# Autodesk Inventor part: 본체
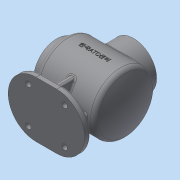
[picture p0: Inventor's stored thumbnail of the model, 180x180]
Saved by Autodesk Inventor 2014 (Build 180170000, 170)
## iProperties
Created: 2023-01
Part Number: 본체
Material: 일반
Document SubType Name: Modeling
Designer: dg
Density: 1 g/cm^3
Appearance: 기본값
Author: dg
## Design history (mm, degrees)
sketch "스케치1"
  geometry: L1 (0, 0)-(122, 0); L2 (0, 38)-(12, 38); L3 (12, 38)-(12, 50); L4 (12, 50)-(111.087, 50); L5 (0, 38)-(0, 27); L6 (0, 27)-(17, 27); L7 (17, 27)-(17, 45); L8 (17, 45)-(107.83, 45); A1 r 120 centre (2, 0) between (122, 0) and (111.087, 50); A2 r 115 centre (2, 0) between (117, 0) and (107.83, 45)
  constraints: 16 end point, 4 point on circle, 3 parallel, 2 centre point, 2 horizontal alignment, 2 perpendicular, 1 concentric, 1 horizontal, 1 point on line, 1 vertical alignment
  dimensions: "d0" = 122 distance of L1.start L1.end; "d1" = 54 diameter of L6 L1; "d2" = 76 diameter of L2 L1; "d3" = 100 diameter of L4 L1; "d4" = 17 distance of L5.end L6.end; "d5" = 110 horizontal distance of L1.end L3.end; "d6" = 120 radius of A1; "d7" = 90 diameter of L8 L1; "d8" = 5 radial gap between concentric circles of A1 A2
revolve "회전1" sketch "스케치1" stored, may be unused: angle "d9" = 90 deg
fillet "모깎기1" dims "d10" = 8
sketch "스케치2"
  geometry: C1 r 38 at (0, 0) reference; 1 further point
  constraints: 1 vertical alignment
  dimensions: "d11" = 32.5 distance of C1.centre point (0, 32.5)
hole "구멍1" sketch "스케치2" at (0, 32.5) diameter "d12" = 3.242; stored, may be unused: countersink angle "d16" = 90 deg, drill point angle "d18" = 118 deg; dims "d13" = 8, "d14" = 4, "d15" = 2, "d17" = 10
node "작업 평면1"
sketch "스케치3"
  geometry: L1 (0, 38)-(0, -38) reference; C1 r 38 at (-63, 0); A1 r 120 centre (-2, 0) between (-113.243, 45) and (-113.243, -45) reference; 2 further points
  constraints: 1 centre point, 1 horizontal alignment, 1 midpoint
  dimensions: "d23" = 76 diameter of C1; "d24" = 63 distance of point (0, 0) C1.centre
extrude "돌출1" join sketch "스케치3" stored distance "d25" = 10; taper "d26" = 0 deg
sketch "스케치4"
  geometry: C1 r 38 at (0, 0) reference; C2 r 27 at (0, 0); 1 further point
  constraints: 1 centre point, 1 coincident
  dimensions: "d27" = 54 diameter of C2
extrude "돌출2" cut sketch "스케치4" stored distance "d28" = 10; taper "d29" = 0 deg
chamfer "모따기1" distance "d30" = 1; stored, may be unused: second distance "d31" = 2, angle "d32" = 45 deg
sketch "스케치5"
  geometry: C1 r 38 at (0, 0) reference; 2 further points
  constraints: 1 vertical alignment
  dimensions: "d33" = 32.5 distance of C1.centre point (0, 32.5)
hole "구멍2" sketch "스케치5" at (0, 32.5) diameter "d34" = 3.242; stored, may be unused: countersink angle "d38" = 90 deg, drill point angle "d40" = 118 deg; dims "d35" = 8, "d36" = 4, "d37" = 2, "d39" = 10
fillet "모깎기2" dims "d44" = 3
chamfer "모따기2" distance "d45" = 1; stored, may be unused: second distance "d46" = 2, angle "d47" = 45 deg
fillet "모깎기3" dims "d48" = 3
node "작업 평면2"
sketch "스케치6"
  geometry: L1 (0, 38)-(0, -38) reference; L2 (-80, 46)-(-46, 46); L3 (-46, -46)-(-80, -46); L4 (-126, 0)-(0, 0); A1 r 46 centre (-46, 0) between (-46, -46) and (-46, 46); A2 r 46 centre (-80, 0) between (-80, 46) and (-80, -46); 2 further points
  constraints: 6 end point, 6 point on circle, 2 centre point, 2 perpendicular, 2 tangent, 1 coincident, 1 equal radius, 1 horizontal alignment, 1 midpoint, 1 parallel
  dimensions: "d50" = 92 distance between parallel lines of L3 L2; "d51" = 126 distance of L4.start point (0, 0)
extrude "돌출3" join sketch "스케치6" distance "d52" = 10; taper "d53" = 0 deg
sketch "스케치7"
  geometry: L1 (46, -46)-(80, -46) reference; L2 (80, 46)-(46, 46) reference; L3 (63, 46)-(63, -46); C1 r 4.5 at (33, 30); C2 r 4.5 at (33, -30); C3 r 4.5 at (93, -30); C4 r 4.5 at (93, 30); A1 r 46 centre (46, 0) between (46, 46) and (46, -46) reference; 1 further point
  constraints: 4 centre point, 3 equal radius, 2 end point, 2 horizontal alignment, 2 midpoint, 2 vertical alignment
  dimensions: "d54" = 60 distance of C4.centre C1.centre; "d55" = 60 distance of C2.centre C1.centre; "d56" = 30 vertical distance of A1.centre C2.centre; "d57" = 9 diameter of C1; "d58" = 30 distance from line of C4.centre L3
extrude "돌출4" cut sketch "스케치7" stored distance "d59" = 10; taper "d60" = 0 deg
sketch "스케치8"
  geometry: L1 (80, 46)-(46, 46) reference; L2 (58, 35)-(68, 35); L3 (68, 35)-(68, -35); L4 (68, -35)-(58, -35); L5 (58, -35)-(58, 35); A1 r 46 centre (46, 0) between (46, 46) and (46, -46) reference; 5 further points
  constraints: 8 end point, 3 midpoint, 2 parallel, 1 horizontal, 1 horizontal alignment, 1 perpendicular, 1 point on circle, 1 vertical alignment
  dimensions: "d61" = 10 distance of L2.start L2.end; "d62" = 70 distance of L4.end L2.start
extrude "돌출5" join sketch "스케치8" stored distance "d63" = 10; taper "d64" = 0 deg
sketch "스케치9"
  geometry: L1 (10.974, 32.5)-(10, 34.121) reference; L2 (10, 34.121)-(0, 34.121) reference; L3 (0, 34.121)-(0, 38) reference; L4 (0, 38)-(9, 38) reference; L5 (12, 41)-(12, 42) reference; L6 (20, 50)-(22, 50) reference; L7 (25, 53)-(25, 64) reference; L8 (25, 64)-(28.879, 64) reference; L9 (28.879, 64)-(28.879, 54) reference; L10 (28.879, 54)-(30.5, 53.026) reference; L11 (30.5, 53.026)-(32.121, 54) reference; L12 (32.121, 54)-(32.121, 64) reference; L13 (32.121, 64)-(35, 64) reference; L14 (35, 64)-(36, 63) reference; L15 (36, 63)-(36, 45) reference; L16 (36, 45)-(20, 45) reference; L17 (17, 42)-(17, 27) reference; L18 (17, 27)-(1, 27) reference; L19 (1, 27)-(0, 28) reference; L20 (0, 28)-(0, 30.879) reference; L21 (0, 30.879)-(10, 30.879) reference; L22 (10, 30.879)-(10.974, 32.5) reference; L23 (126, -70)-(126, -80) reference; L24 (126, -80)-(0, -80) reference; L25 (0, -80)-(0, -70) reference; L26 (0, -70)-(58, -70) reference; L27 (58, -70)-(58, -50) reference; L28 (58, -50)-(20, -50) reference; L29 (12, -42)-(12, -41) reference; L30 (9, -38)-(0, -38) reference; L31 (0, -38)-(0, -34.121) reference; L32 (0, -34.121)-(10, -34.121) reference; L33 (10, -34.121)-(10.974, -32.5) reference; L34 (10.974, -32.5)-(10, -30.879) reference; L35 (10, -30.879)-(0, -30.879) reference; L36 (0, -30.879)-(0, -28) reference; L37 (0, -28)-(1, -27) reference; L38 (1, -27)-(17, -27) reference; L39 (17, -27)-(17, -42) reference; L40 (20, -45)-(105.827, -45) reference; L41 (105.827, 45)-(90, 45) reference; L42 (90, 45)-(90, 63) reference; L43 (90, 63)-(91, 64) reference; L44 (91, 64)-(93.879, 64) reference; L45 (93.879, 64)-(93.879, 54) reference; L46 (93.879, 54)-(95.5, 53.026) reference; L47 (95.5, 53.026)-(97.121, 54) reference; L48 (97.121, 54)-(97.121, 64) reference; L49 (97.121, 64)-(101, 64) reference; L50 (101, 64)-(101, 53) reference; L51 (104, 50)-(105.827, 50) reference; L52 (105.827, -50)-(68, -50) reference; L53 (68, -50)-(68, -70) reference; L54 (68, -70)-(126, -70) reference; L55 (91, 64)-(35, 64) reference; L56 (63, -80)-(63, 64); L57 (23, -70)-(28.359, -50); A1 r 3 centre (9, 41) between (9, 38) and (12, 41) reference; A2 r 8 centre (20, 42) between (20, 50) and (12, 42) reference; A3 r 3 centre (20, 42) between (20, 45) and (17, 42) reference; A4 r 8 centre (20, -42) between (12, -42) and (20, -50) reference; A5 r 3 centre (9, -41) between (12, -41) and (9, -38) reference; A6 r 3 centre (20, -42) between (17, -42) and (20, -45) reference; A7 r 3 centre (105.827, -42) between (105.827, -45) and (108.608, -43.125) reference; A8 r 115 centre (2, 0) between (108.608, -43.125) and (108.608, 43.125) reference; A9 r 3 centre (105.827, 42) between (108.608, 43.125) and (105.827, 45) reference; A10 r 8 centre (105.827, 42) between (113.243, 45) and (105.827, 50) reference; A11 r 120 centre (2, 0) between (113.243, -45) and (113.243, 45) reference; A12 r 8 centre (105.827, -42) between (105.827, -50) and (113.243, -45) reference; 1 further point
  constraints: 4 end point, 2 midpoint, 2 point on line, 2 other
  dimensions: "d65" = 105 deg angle of L26 L57; "d66" = 40 horizontal distance of L56.start L57.start
feature "리브1" sketch "스케치9" dims "d67" = 1, "d68" = 10, "d69" = 0, "d70" = 0, "d71" = 1, "d72" = 1
sketch "스케치10"
  geometry: L1 (10, -34.121)-(10.974, -32.5) reference; L2 (10.974, -32.5)-(10, -30.879) reference; L3 (10, -30.879)-(0, -30.879) reference; L4 (0, -30.879)-(0, -28) reference; L5 (0, -28)-(1, -27) reference; L6 (1, -27)-(17, -27) reference; L7 (17, -27)-(17, -42) reference; L8 (20, -45)-(105.827, -45) reference; L9 (105.827, 45)-(90, 45) reference; L10 (90, 45)-(90, 63) reference; L11 (90, 63)-(91, 64) reference; L12 (91, 64)-(93.879, 64) reference; L13 (93.879, 64)-(93.879, 54) reference; L14 (93.879, 54)-(95.5, 53.026) reference; L15 (95.5, 53.026)-(97.121, 54) reference; L16 (97.121, 54)-(97.121, 64) reference; L17 (97.121, 64)-(101, 64) reference; L18 (101, 64)-(101, 53) reference; L19 (104, 50)-(105.827, 50) reference; L20 (105.827, -50)-(68, -50) reference; L21 (68, -50)-(68, -70) reference; L22 (68, -70)-(126, -70) reference; L23 (126, -70)-(126, -80) reference; L24 (126, -80)-(0, -80) reference; L25 (0, -80)-(0, -70) reference; L26 (0, -70)-(23, -70) reference; L27 (23, -70)-(28.359, -50) reference; L28 (28.359, -50)-(20, -50) reference; L29 (12, -42)-(12, -41) reference; L30 (9, -38)-(0, -38) reference; L31 (0, -38)-(0, -34.121) reference; L32 (0, -34.121)-(10, -34.121) reference; L33 (10.974, 32.5)-(10, 34.121) reference; L34 (10, 34.121)-(0, 34.121) reference; L35 (0, 34.121)-(0, 38) reference; L36 (0, 38)-(9, 38) reference; L37 (12, 41)-(12, 42) reference; L38 (20, 50)-(22, 50) reference; L39 (25, 53)-(25, 64) reference; L40 (25, 64)-(28.879, 64) reference; L41 (28.879, 64)-(28.879, 54) reference; L42 (28.879, 54)-(30.5, 53.026) reference; L43 (30.5, 53.026)-(32.121, 54) reference; L44 (32.121, 54)-(32.121, 64) reference; L45 (32.121, 64)-(35, 64) reference; L46 (35, 64)-(36, 63) reference; L47 (36, 63)-(36, 45) reference; L48 (36, 45)-(20, 45) reference; L49 (17, 42)-(17, 27) reference; L50 (17, 27)-(1, 27) reference; L51 (1, 27)-(0, 28) reference; L52 (0, 28)-(0, 30.879) reference; L53 (0, 30.879)-(10, 30.879) reference; L54 (10, 30.879)-(10.974, 32.5) reference; L55 (97.641, -50)-(103, -70); L56 (91, 64)-(35, 64) reference; L57 (63, 64)-(63, -80); A1 r 3 centre (20, -42) between (17, -42) and (20, -45) reference; A2 r 3 centre (105.827, -42) between (105.827, -45) and (108.608, -43.125) reference; A3 r 115 centre (2, 0) between (108.608, -43.125) and (108.608, 43.125) reference; A4 r 3 centre (105.827, 42) between (108.608, 43.125) and (105.827, 45) reference; A5 r 8 centre (105.827, 42) between (113.243, 45) and (105.827, 50) reference; A6 r 120 centre (2, 0) between (113.243, -45) and (113.243, 45) reference; A7 r 8 centre (105.827, -42) between (105.827, -50) and (113.243, -45) reference; A8 r 8 centre (20, -42) between (12, -42) and (20, -50) reference; A9 r 3 centre (9, -41) between (12, -41) and (9, -38) reference; A10 r 3 centre (9, 41) between (9, 38) and (12, 41) reference; A11 r 8 centre (20, 42) between (20, 50) and (12, 42) reference; A12 r 3 centre (20, 42) between (20, 45) and (17, 42) reference; 1 further point
  constraints: 4 end point, 2 midpoint, 2 point on line, 2 other
  dimensions: "d73" = 105 deg angle of L22 L55; "d74" = 40 horizontal distance of L55.end L57.end
feature "리브2" sketch "스케치10" dims "d75" = 1, "d76" = 10, "d77" = 0, "d78" = 0, "d79" = 1, "d80" = 1
fillet "모깎기4" dims "d81" = 3
fillet "모깎기5" dims "d82" = 3
node "작업 평면3"
sketch "스케치11"
  geometry: L1 (0, -38)-(0, 38) reference; L2 (97.5, -80)-(88.5, -80) reference; L3 (37.5, -80)-(28.5, -80) reference; L4 (37.5, -80)-(28.5, -80) reference; L5 (97.5, -80)-(88.5, -80) reference; L6 (46, -80)-(46, -80) reference; L7 (46, -80)-(80, -80) reference; L8 (80, -80)-(80, -80) reference; L9 (80, -80)-(46, -80) reference; L10 (80, -80)-(126, -80) reference; 2 further points
  constraints: 1 other
  dimensions: "d84" = 80 distance from line of L10 point (63, 0); "d85" = 63 distance from line of L1 point (63, 0)
feature "엠보싱1" sketch "스케치11" dims "d0" = 122, "d1" = 54, "d2" = 76, "d3" = 100, "d4" = 17, "d5" = 110, "d6" = 120, "d7" = 90, "d8" = 5, "d13" = 8, "d86" = 0.5, "d87" = 0
node "솔리드1"
pattern_circular "원형 패턴1" dims angle "d20" = 360 deg
pattern_circular "원형 패턴2" dims angle "d42" = 360 deg
node "투영된 루프1"
node "절단 모서리 투영1"
node "절단 모서리 투영2"
other parameters: "d22" = 64, "d83" = 50.5
